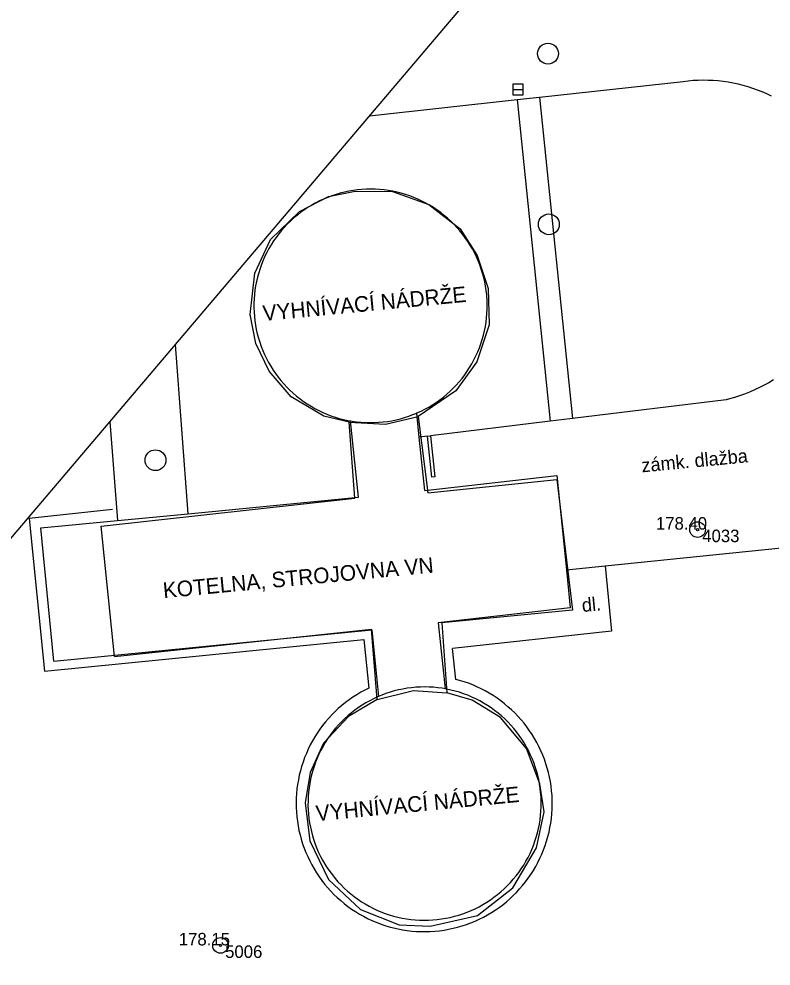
# Model space of a CAD drawing. Extents: x -540150 to -533593, y -1185082 to -1180066.
# Drawn here: x -536809.96 to -536773.87, y -1184142.25 to -1184096.8 of the extents above; entities that cross this region are included whole.
import ezdxf

# ---------------------------------------------------------------- set-up
doc = ezdxf.new("R2010")
doc.units = 0
for name, color, linetype in [('KN_VKP_HRAN_', 7, 'Continuous'), ('rámeček', 7, 'Continuous'), ('Vrstva 10', 7, 'Continuous'), ('Vrstva 11', 7, 'Continuous'), ('Vrstva 21', 7, 'Continuous'), ('Vrstva 22', 7, 'Continuous'), ('Vrstva 23', 7, 'Continuous'), ('Vrstva 27', 7, 'Continuous'), ('Vrstva 40', 7, 'Continuous'), ('Vrstva 41', 7, 'Continuous'), ('Vrstva 5', 7, 'Continuous')]:
    doc.layers.add(name, color=color, linetype=linetype)

msp = doc.modelspace()

# ---------------------------------------------------------------- linework, layer by layer
at = {"layer": 'KN_VKP_HRAN_'}
for p, q in [((-536795.101, -1184105.315), (-536793.821, -1184105.065)), ((-536793.821, -1184105.065), (-536792.031, -1184105.085)), ((-536792.031, -1184105.085), (-536790.291, -1184105.705)), ((-536796.501, -1184106.035), (-536795.101, -1184105.315)), ((-536797.891, -1184107.385), (-536796.501, -1184106.035)), ((-536790.291, -1184105.705), (-536788.791, -1184106.875)), ((-536788.791, -1184106.875), (-536787.971, -1184108.155)), ((-536798.641, -1184109.005), (-536797.891, -1184107.385)), ((-536787.971, -1184108.155), (-536787.451, -1184109.735)), ((-536798.861, -1184110.975), (-536798.641, -1184109.005)), ((-536787.451, -1184109.735), (-536787.401, -1184111.475)), ((-536798.601, -1184112.375), (-536798.861, -1184110.975)), ((-536787.401, -1184111.475), (-536787.991, -1184113.255)), ((-536797.961, -1184113.695), (-536798.601, -1184112.375)), ((-536787.991, -1184113.255), (-536789.001, -1184114.645)), ((-536796.901, -1184114.925), (-536797.961, -1184113.695)), ((-536789.001, -1184114.645), (-536790.811, -1184115.875)), ((-536795.331, -1184115.855), (-536796.901, -1184114.925)), ((-536794.111, -1184116.155), (-536795.331, -1184115.855)), ((-536792.371, -1184116.245), (-536790.811, -1184115.875)), ((-536790.811, -1184115.875), (-536790.341, -1184119.545)), ((-536794.111, -1184116.155), (-536792.371, -1184116.245)), ((-536793.841, -1184119.795), (-536794.111, -1184116.155)), ((-536790.341, -1184119.545), (-536784.141, -1184118.895)), ((-536784.141, -1184118.895), (-536783.401, -1184125.165)), ((-536806.021, -1184121.135), (-536793.841, -1184119.795)), ((-536805.371, -1184127.395), (-536806.021, -1184121.135)), ((-536783.401, -1184125.165), (-536789.661, -1184125.785)), ((-536789.661, -1184125.785), (-536789.421, -1184129.135)), ((-536805.371, -1184127.395), (-536793.041, -1184126.085)), ((-536792.771, -1184129.455), (-536793.041, -1184126.085)), ((-536792.771, -1184129.455), (-536791.031, -1184129.025)), ((-536791.031, -1184129.025), (-536789.421, -1184129.135)), ((-536788.211, -1184129.495), (-536789.421, -1184129.135)), ((-536792.771, -1184129.455), (-536794.141, -1184130.275)), ((-536786.851, -1184130.325), (-536788.211, -1184129.495)), ((-536794.141, -1184130.275), (-536795.341, -1184131.555)), ((-536785.601, -1184131.815), (-536786.851, -1184130.325)), ((-536795.341, -1184131.555), (-536795.981, -1184132.955)), ((-536784.961, -1184133.495), (-536785.601, -1184131.815)), ((-536795.981, -1184132.955), (-536796.221, -1184134.415)), ((-536784.761, -1184134.845), (-536784.961, -1184133.495)), ((-536796.221, -1184134.415), (-536796.001, -1184136.245)), ((-536785.131, -1184136.575), (-536784.761, -1184134.845)), ((-536796.001, -1184136.245), (-536795.111, -1184138.095)), ((-536786.261, -1184138.485), (-536785.131, -1184136.575)), ((-536795.111, -1184138.095), (-536793.571, -1184139.525)), ((-536787.961, -1184139.825), (-536786.261, -1184138.485)), ((-536793.571, -1184139.525), (-536791.721, -1184140.275)), ((-536790.221, -1184140.335), (-536787.961, -1184139.825)), ((-536791.721, -1184140.275), (-536790.221, -1184140.335))]:
    msp.add_line(p, q, dxfattribs=at)
at = {"layer": 'rámeček'}
msp.add_lwpolyline([(-536863.363, -1184184.148), (-536677.591, -1183965.383), (-535884.856, -1184638.563), (-536070.628, -1184857.328)], close=True, dxfattribs=at)
at = {"layer": 'Vrstva 10'}
for p, q in [((-536801.835, -1184120.54), (-536802.454, -1184112.422)), ((-536805.597, -1184116.122), (-536805.237, -1184120.869)), ((-536790.36, -1184116.823), (-536790.752, -1184116.871))]:
    msp.add_line(p, q, dxfattribs=at)
for points in [[(-536793.14, -1184101.453), (-536786.059, -1184100.673), (-536784.988, -1184100.555), (-536778.091, -1184099.795)], [(-536778.091, -1184099.795), (-536777.851, -1184099.766), (-536777.61, -1184099.746), (-536777.369, -1184099.733), (-536777.128, -1184099.728), (-536776.886, -1184099.731), (-536776.645, -1184099.743), (-536776.404, -1184099.762), (-536776.164, -1184099.789), (-536775.925, -1184099.824), (-536775.687, -1184099.867), (-536775.451, -1184099.918), (-536775.216, -1184099.977), (-536774.984, -1184100.043), (-536774.754, -1184100.117), (-536774.527, -1184100.199), (-536774.302, -1184100.288), (-536774.08, -1184100.384), (-536773.862, -1184100.488)], [(-536773.754, -1184114.124), (-536773.975, -1184114.254), (-536774.2, -1184114.377), (-536774.429, -1184114.493), (-536774.662, -1184114.602), (-536774.897, -1184114.703), (-536775.136, -1184114.798), (-536775.377, -1184114.884), (-536775.622, -1184114.963), (-536775.868, -1184115.035), (-536776.021, -1184115.075)], [(-536776.021, -1184115.075), (-536783.4, -1184115.972), (-536783.921, -1184116.035)], [(-536783.921, -1184116.035), (-536784.468, -1184116.102), (-536790.211, -1184116.805)], [(-536783.689, -1184123.23), (-536781.823, -1184123.039), (-536770.396, -1184121.867), (-536769.948, -1184121.821)]]:
    msp.add_lwpolyline(points, dxfattribs=at)
at = {"layer": 'Vrstva 11'}
for p, q in [((-536784.988, -1184100.555), (-536783.4, -1184115.972)), ((-536786.059, -1184100.673), (-536784.468, -1184116.102)), ((-536790.15, -1184118.791), (-536790.36, -1184116.823)), ((-536790.001, -1184118.775), (-536790.15, -1184118.791)), ((-536805.481, -1184120.345), (-536809.471, -1184120.775)), ((-536809.471, -1184120.775), (-536808.741, -1184128.095)), ((-536781.823, -1184123.039), (-536781.521, -1184126.185)), ((-536781.521, -1184126.185), (-536789.161, -1184127.007)), ((-536808.741, -1184128.095), (-536793.408, -1184126.576)), ((-536793.408, -1184126.576), (-536793.169, -1184128.905)), ((-536789.001, -1184128.491), (-536789.161, -1184127.007))]:
    msp.add_line(p, q, dxfattribs=at)
for points in [[(-536790.36, -1184116.823), (-536790.211, -1184116.805), (-536790.001, -1184118.775)], [(-536785.65, -1184138.205), (-536785.518, -1184138.027), (-536785.392, -1184137.845), (-536785.273, -1184137.658), (-536785.16, -1184137.467), (-536785.055, -1184137.272), (-536784.957, -1184137.073), (-536784.865, -1184136.871), (-536784.782, -1184136.665), (-536784.706, -1184136.457), (-536784.637, -1184136.246), (-536784.576, -1184136.033), (-536784.522, -1184135.818), (-536784.477, -1184135.601), (-536784.439, -1184135.382), (-536784.41, -1184135.163), (-536784.388, -1184134.942), (-536784.374, -1184134.721), (-536784.368, -1184134.499), (-536784.37, -1184134.277), (-536784.38, -1184134.056), (-536784.399, -1184133.835), (-536784.425, -1184133.615), (-536784.459, -1184133.396), (-536784.501, -1184133.178), (-536784.55, -1184132.962), (-536784.608, -1184132.748), (-536784.673, -1184132.536), (-536784.746, -1184132.326), (-536784.826, -1184132.12), (-536784.914, -1184131.916), (-536785.009, -1184131.716), (-536785.111, -1184131.519), (-536785.22, -1184131.326), (-536785.336, -1184131.137), (-536785.459, -1184130.952), (-536785.588, -1184130.772), (-536785.724, -1184130.597), (-536785.866, -1184130.427), (-536786.014, -1184130.262), (-536786.168, -1184130.102), (-536786.328, -1184129.948), (-536786.493, -1184129.8), (-536786.663, -1184129.658), (-536786.838, -1184129.522), (-536787.018, -1184129.393), (-536787.203, -1184129.27), (-536787.392, -1184129.154), (-536787.585, -1184129.045), (-536787.782, -1184128.943), (-536787.982, -1184128.848), (-536788.186, -1184128.76), (-536788.392, -1184128.68), (-536788.602, -1184128.607), (-536788.814, -1184128.542), (-536789.001, -1184128.491)], [(-536793.169, -1184128.905), (-536793.367, -1184129.005), (-536793.562, -1184129.111), (-536793.752, -1184129.224), (-536793.939, -1184129.345), (-536794.12, -1184129.472), (-536794.298, -1184129.605), (-536794.47, -1184129.745), (-536794.637, -1184129.89), (-536794.799, -1184130.042), (-536794.955, -1184130.199), (-536795.105, -1184130.362), (-536795.249, -1184130.531), (-536795.388, -1184130.704), (-536795.52, -1184130.882), (-536795.645, -1184131.065), (-536795.764, -1184131.252), (-536795.875, -1184131.444), (-536795.98, -1184131.639), (-536796.078, -1184131.838), (-536796.169, -1184132.041), (-536796.252, -1184132.246), (-536796.327, -1184132.455), (-536796.396, -1184132.666), (-536796.456, -1184132.879), (-536796.509, -1184133.094), (-536796.554, -1184133.311), (-536796.591, -1184133.53), (-536796.62, -1184133.75), (-536796.641, -1184133.971), (-536796.654, -1184134.192), (-536796.66, -1184134.414), (-536796.657, -1184134.635), (-536796.646, -1184134.857), (-536796.627, -1184135.078), (-536796.601, -1184135.298), (-536796.566, -1184135.517), (-536796.524, -1184135.734), (-536796.473, -1184135.95), (-536796.415, -1184136.164), (-536796.349, -1184136.376), (-536796.276, -1184136.585), (-536796.195, -1184136.792), (-536796.107, -1184136.995), (-536796.011, -1184137.195), (-536795.909, -1184137.392), (-536795.799, -1184137.585), (-536795.683, -1184137.773), (-536795.559, -1184137.957), (-536795.429, -1184138.137), (-536795.293, -1184138.312), (-536795.151, -1184138.482), (-536795.002, -1184138.647), (-536794.848, -1184138.806), (-536794.688, -1184138.959), (-536794.522, -1184139.107), (-536794.352, -1184139.248), (-536794.176, -1184139.384), (-536793.996, -1184139.513), (-536793.811, -1184139.635), (-536793.621, -1184139.75), (-536793.428, -1184139.859), (-536793.231, -1184139.961), (-536793.03, -1184140.055), (-536792.826, -1184140.142), (-536792.62, -1184140.222), (-536792.41, -1184140.294), (-536792.198, -1184140.359), (-536791.983, -1184140.416), (-536791.767, -1184140.465), (-536791.549, -1184140.506), (-536791.33, -1184140.539), (-536791.11, -1184140.565), (-536790.889, -1184140.582), (-536790.667, -1184140.592), (-536790.446, -1184140.594), (-536790.224, -1184140.587), (-536790.003, -1184140.573), (-536789.782, -1184140.55), (-536789.563, -1184140.52), (-536789.344, -1184140.482), (-536789.127, -1184140.435), (-536788.912, -1184140.382), (-536788.699, -1184140.32), (-536788.489, -1184140.251), (-536788.281, -1184140.174), (-536788.075, -1184140.09), (-536787.874, -1184139.998), (-536787.675, -1184139.899), (-536787.48, -1184139.793), (-536787.289, -1184139.68), (-536787.103, -1184139.561), (-536786.921, -1184139.434), (-536786.743, -1184139.301), (-536786.571, -1184139.162)], [(-536786.571, -1184139.162), (-536786.403, -1184139.017), (-536786.241, -1184138.866), (-536786.084, -1184138.709), (-536785.934, -1184138.546), (-536785.789, -1184138.378), (-536785.65, -1184138.205)]]:
    msp.add_lwpolyline(points, dxfattribs=at)
at = {"layer": 'Vrstva 21'}
for centre, radius in [((-536777.391, -1184121.305), 0.375), ((-536777.391, -1184121.305), 0.05), ((-536800.291, -1184141.255), 0.375), ((-536800.291, -1184141.255), 0.05)]:
    msp.add_circle(centre, radius, dxfattribs=at)
at = {"layer": 'Vrstva 27'}
msp.add_line((-536786.261, -1184100.185), (-536785.761, -1184100.185), dxfattribs=at)
msp.add_lwpolyline([(-536786.261, -1184100.435), (-536785.761, -1184100.435), (-536785.761, -1184099.935), (-536786.261, -1184099.935)], close=True, dxfattribs=at)
for centre in [(-536784.571, -1184098.465), (-536784.531, -1184106.655), (-536803.411, -1184117.975)]:
    msp.add_circle(centre, 0.5, dxfattribs=at)
at = {"layer": 'Vrstva 5'}
for p, q in [((-536793.675, -1184119.751), (-536794.053, -1184116.086)), ((-536790.491, -1184119.425), (-536784.151, -1184118.715)), ((-536808.283, -1184127.621), (-536808.921, -1184121.225)), ((-536794.923, -1184137.875), (-536794.79, -1184138.04)), ((-536794.79, -1184138.04), (-536794.652, -1184138.2))]:
    msp.add_line(p, q, dxfattribs=at)
for points in [[(-536787.514, -1184110.041), (-536787.538, -1184109.831), (-536787.569, -1184109.621), (-536787.609, -1184109.413), (-536787.657, -1184109.207), (-536787.712, -1184109.003), (-536787.775, -1184108.801), (-536787.846, -1184108.601), (-536787.924, -1184108.405), (-536788.01, -1184108.211), (-536788.102, -1184108.021), (-536788.202, -1184107.834), (-536788.309, -1184107.652), (-536788.423, -1184107.473), (-536788.543, -1184107.299), (-536788.67, -1184107.13), (-536788.803, -1184106.965), (-536788.942, -1184106.806), (-536789.088, -1184106.652), (-536789.239, -1184106.503), (-536789.395, -1184106.361), (-536789.557, -1184106.224), (-536789.723, -1184106.094), (-536789.895, -1184105.97), (-536790.071, -1184105.853), (-536790.252, -1184105.742), (-536790.436, -1184105.638), (-536790.624, -1184105.541), (-536790.816, -1184105.452), (-536791.011, -1184105.37), (-536791.209, -1184105.295), (-536791.41, -1184105.228), (-536791.613, -1184105.168), (-536791.818, -1184105.116), (-536792.025, -1184105.072), (-536792.234, -1184105.036), (-536792.443, -1184105.007), (-536792.654, -1184104.987), (-536792.865, -1184104.975), (-536793.077, -1184104.97), (-536793.288, -1184104.974), (-536793.5, -1184104.985), (-536793.711, -1184105.005), (-536793.92, -1184105.032), (-536794.129, -1184105.068), (-536794.336, -1184105.111), (-536794.542, -1184105.162), (-536794.745, -1184105.221), (-536794.946, -1184105.287), (-536795.144, -1184105.361), (-536795.34, -1184105.443), (-536795.532, -1184105.531), (-536795.72, -1184105.627), (-536795.905, -1184105.73), (-536796.086, -1184105.84), (-536796.263, -1184105.957), (-536796.435, -1184106.08), (-536796.602, -1184106.21), (-536796.764, -1184106.346), (-536796.921, -1184106.488), (-536797.073, -1184106.635), (-536797.219, -1184106.789), (-536797.359, -1184106.947), (-536797.492, -1184107.111), (-536797.62, -1184107.28), (-536797.741, -1184107.454), (-536797.856, -1184107.632), (-536797.963, -1184107.814), (-536798.064, -1184108), (-536798.157, -1184108.19), (-536798.244, -1184108.383), (-536798.323, -1184108.58), (-536798.394, -1184108.779), (-536798.458, -1184108.981), (-536798.514, -1184109.185), (-536798.563, -1184109.391), (-536798.603, -1184109.599), (-536798.636, -1184109.808), (-536798.661, -1184110.018), (-536798.678, -1184110.229), (-536798.687, -1184110.44), (-536798.688, -1184110.652), (-536798.68, -1184110.863), (-536798.665, -1184111.075), (-536798.642, -1184111.285), (-536798.611, -1184111.494), (-536798.572, -1184111.702), (-536798.526, -1184111.909), (-536798.471, -1184112.113), (-536798.409, -1184112.316), (-536798.339, -1184112.515), (-536798.262, -1184112.712), (-536798.177, -1184112.906), (-536798.085, -1184113.097), (-536797.986, -1184113.284)], [(-536797.251, -1184114.316), (-536797.106, -1184114.471), (-536796.956, -1184114.62), (-536796.8, -1184114.763), (-536796.639, -1184114.9), (-536796.473, -1184115.031), (-536796.302, -1184115.156), (-536796.126, -1184115.274), (-536795.946, -1184115.385), (-536795.762, -1184115.49), (-536795.574, -1184115.588), (-536795.383, -1184115.678), (-536795.188, -1184115.761), (-536794.991, -1184115.837), (-536794.79, -1184115.905), (-536794.588, -1184115.965), (-536794.383, -1184116.018), (-536794.176, -1184116.063), (-536794.053, -1184116.086), (-536793.967, -1184116.1), (-536793.758, -1184116.13), (-536793.547, -1184116.151), (-536793.336, -1184116.164), (-536793.124, -1184116.17), (-536792.913, -1184116.167), (-536792.701, -1184116.156), (-536792.491, -1184116.138), (-536792.281, -1184116.111), (-536792.072, -1184116.077), (-536791.864, -1184116.034), (-536791.659, -1184115.984), (-536791.455, -1184115.926), (-536791.254, -1184115.861), (-536791.055, -1184115.788), (-536790.871, -1184115.712), (-536790.86, -1184115.707), (-536790.667, -1184115.619), (-536790.478, -1184115.524), (-536790.293, -1184115.422), (-536790.111, -1184115.313), (-536789.934, -1184115.197), (-536789.762, -1184115.074), (-536789.594, -1184114.946), (-536789.431, -1184114.81), (-536789.273, -1184114.669), (-536789.121, -1184114.522), (-536788.975, -1184114.369), (-536788.834, -1184114.211), (-536788.699, -1184114.048), (-536788.571, -1184113.879), (-536788.449, -1184113.706), (-536788.334, -1184113.529), (-536788.226, -1184113.347), (-536788.124, -1184113.161), (-536788.03, -1184112.972), (-536787.943, -1184112.779), (-536787.863, -1184112.583), (-536787.791, -1184112.384), (-536787.726, -1184112.183), (-536787.669, -1184111.979), (-536787.619, -1184111.773), (-536787.578, -1184111.565), (-536787.544, -1184111.356), (-536787.518, -1184111.146), (-536787.501, -1184110.936), (-536787.491, -1184110.724), (-536787.489, -1184110.512), (-536787.495, -1184110.301), (-536787.509, -1184110.09), (-536787.514, -1184110.041)], [(-536797.986, -1184113.284), (-536797.88, -1184113.467), (-536797.767, -1184113.646), (-536797.648, -1184113.821), (-536797.522, -1184113.991), (-536797.389, -1184114.156), (-536797.251, -1184114.316)], [(-536790.491, -1184119.425), (-536790.752, -1184116.871), (-536790.871, -1184115.712)], [(-536784.151, -1184118.715), (-536783.689, -1184123.23), (-536783.501, -1184125.065)], [(-536808.921, -1184121.225), (-536805.237, -1184120.869), (-536801.835, -1184120.54), (-536793.675, -1184119.751)], [(-536783.501, -1184125.065), (-536789.839, -1184125.782), (-536789.515, -1184128.942)], [(-536808.283, -1184127.621), (-536793.027, -1184126.11), (-536792.7, -1184129.307)], [(-536784.925, -1184133.923), (-536784.949, -1184133.713), (-536784.981, -1184133.503), (-536785.02, -1184133.296), (-536785.068, -1184133.09), (-536785.123, -1184132.885), (-536785.186, -1184132.683), (-536785.257, -1184132.484), (-536785.335, -1184132.287), (-536785.421, -1184132.094), (-536785.513, -1184131.904), (-536785.613, -1184131.717), (-536785.72, -1184131.534), (-536785.834, -1184131.356), (-536785.954, -1184131.182), (-536786.081, -1184131.013), (-536786.214, -1184130.848), (-536786.353, -1184130.689), (-536786.499, -1184130.535), (-536786.65, -1184130.387), (-536786.806, -1184130.244), (-536786.968, -1184130.108), (-536787.134, -1184129.977), (-536787.306, -1184129.854), (-536787.482, -1184129.736), (-536787.662, -1184129.626), (-536787.847, -1184129.522), (-536788.035, -1184129.425), (-536788.227, -1184129.336), (-536788.422, -1184129.254), (-536788.62, -1184129.179), (-536788.82, -1184129.112), (-536789.023, -1184129.052), (-536789.229, -1184129.001), (-536789.436, -1184128.957), (-536789.515, -1184128.942), (-536789.644, -1184128.92), (-536789.854, -1184128.892), (-536790.064, -1184128.872), (-536790.276, -1184128.86), (-536790.487, -1184128.855), (-536790.699, -1184128.859), (-536790.91, -1184128.871), (-536791.121, -1184128.89), (-536791.33, -1184128.918), (-536791.539, -1184128.953), (-536791.746, -1184128.997), (-536791.951, -1184129.048), (-536792.155, -1184129.107), (-536792.355, -1184129.173), (-536792.554, -1184129.247), (-536792.7, -1184129.307), (-536792.749, -1184129.329), (-536792.941, -1184129.417), (-536793.129, -1184129.513), (-536793.314, -1184129.617), (-536793.495, -1184129.727), (-536793.671, -1184129.843), (-536793.843, -1184129.967), (-536794.01, -1184130.096), (-536794.173, -1184130.232), (-536794.329, -1184130.374), (-536794.481, -1184130.522), (-536794.627, -1184130.676), (-536794.766, -1184130.834), (-536794.9, -1184130.998), (-536795.027, -1184131.167), (-536795.148, -1184131.341), (-536795.263, -1184131.519), (-536795.37, -1184131.701), (-536795.471, -1184131.887), (-536795.564, -1184132.077), (-536795.65, -1184132.271), (-536795.729, -1184132.467), (-536795.8, -1184132.666), (-536795.864, -1184132.868), (-536795.92, -1184133.072), (-536795.968, -1184133.278), (-536796.008, -1184133.486), (-536796.041, -1184133.695), (-536796.066, -1184133.905), (-536796.082, -1184134.116), (-536796.091, -1184134.327), (-536796.092, -1184134.539), (-536796.085, -1184134.75), (-536796.069, -1184134.961), (-536796.046, -1184135.172), (-536796.015, -1184135.381), (-536795.976, -1184135.589), (-536795.929, -1184135.795), (-536795.874, -1184135.999), (-536795.812, -1184136.202), (-536795.742, -1184136.401), (-536795.664, -1184136.598), (-536795.58, -1184136.792)], [(-536794.652, -1184138.2), (-536794.507, -1184138.355), (-536794.357, -1184138.503), (-536794.201, -1184138.646), (-536794.039, -1184138.783), (-536793.873, -1184138.914), (-536793.702, -1184139.039), (-536793.526, -1184139.157), (-536793.346, -1184139.268), (-536793.162, -1184139.372), (-536792.974, -1184139.469), (-536792.783, -1184139.559), (-536792.588, -1184139.642), (-536792.391, -1184139.718), (-536792.19, -1184139.785), (-536791.987, -1184139.846), (-536791.782, -1184139.898), (-536791.576, -1184139.943), (-536791.367, -1184139.98), (-536791.158, -1184140.009), (-536790.947, -1184140.03), (-536790.736, -1184140.043), (-536790.524, -1184140.048), (-536790.313, -1184140.045), (-536790.101, -1184140.034), (-536789.891, -1184140.015), (-536789.681, -1184139.988), (-536789.472, -1184139.954), (-536789.265, -1184139.911), (-536789.059, -1184139.86), (-536788.856, -1184139.802), (-536788.655, -1184139.736), (-536788.456, -1184139.663), (-536788.261, -1184139.582), (-536788.069, -1184139.494), (-536787.88, -1184139.399), (-536787.695, -1184139.296), (-536787.513, -1184139.187), (-536787.337, -1184139.071), (-536787.164, -1184138.948), (-536786.997, -1184138.819), (-536786.834, -1184138.684), (-536786.677, -1184138.542), (-536786.525, -1184138.395), (-536786.379, -1184138.242), (-536786.238, -1184138.084), (-536786.104, -1184137.92), (-536785.976, -1184137.751), (-536785.855, -1184137.578), (-536785.74, -1184137.401), (-536785.632, -1184137.219), (-536785.53, -1184137.033), (-536785.436, -1184136.843), (-536785.35, -1184136.65), (-536785.27, -1184136.454), (-536785.198, -1184136.255), (-536785.134, -1184136.054), (-536785.077, -1184135.85), (-536785.028, -1184135.644), (-536784.987, -1184135.436), (-536784.954, -1184135.228), (-536784.928, -1184135.017), (-536784.911, -1184134.807), (-536784.902, -1184134.595), (-536784.9, -1184134.384), (-536784.907, -1184134.172), (-536784.921, -1184133.961), (-536784.925, -1184133.923)], [(-536795.58, -1184136.792), (-536795.487, -1184136.983), (-536795.388, -1184137.169), (-536795.282, -1184137.352), (-536795.169, -1184137.531), (-536795.049, -1184137.706), (-536794.923, -1184137.875)]]:
    msp.add_lwpolyline(points, dxfattribs=at)

# ---------------------------------------------------------------- texts
at = {"layer": 'Vrstva 22'}
for s, p in [('178.40 ', (-536779.391, -1184121.305)), ('178.15 ', (-536802.291, -1184141.255))]:
    msp.add_text(s, height=0.6, dxfattribs=at).set_placement(p)
at = {"layer": 'Vrstva 23'}
for s, p in [(' 4033', (-536777.391, -1184121.905)), (' 5006', (-536800.291, -1184141.855))]:
    msp.add_text(s, height=0.6, dxfattribs=at).set_placement(p)
at = {"layer": 'Vrstva 40'}
for s, p in [('zámk. dlažba', (-536780.057, -1184118.558)), ('dl.', (-536782.917, -1184125.26))]:
    msp.add_text(s, height=0.65, rotation=5.4216, dxfattribs=at).set_placement(p)
at = {"layer": 'Vrstva 41'}
for s, p in [('VYHNÍVACÍ NÁDRŽE', (-536798.229, -1184111.3)), ('KOTELNA, STROJOVNA VN', (-536803.017, -1184124.597)), ('VYHNÍVACÍ NÁDRŽE', (-536795.68, -1184135.295))]:
    msp.add_text(s, height=0.75, rotation=5.4216, dxfattribs=at).set_placement(p)

doc.saveas('drawing.dxf')
